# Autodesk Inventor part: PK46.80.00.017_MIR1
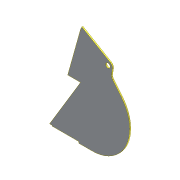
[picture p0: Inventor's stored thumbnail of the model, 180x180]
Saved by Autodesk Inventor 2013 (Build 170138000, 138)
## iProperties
Created: 2004-12
Part Number: PK46.80.00.017_MIR1
Material: Steel, Mild
Document SubType Name: Modeling
Designer: hoeyj
Manufacturer: Standard
Standards Organization: Custom
Density: 7.86 g/cm^3
Mass: 57972.3 g
Surface Area: 12737.7 cm^2
Volume: 7375.62 cm^3
Author: Salex
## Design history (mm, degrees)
derived "PK46.80.00.017.ipt"
  sketch "Sketch1"
    geometry: L1 (384.873, 16.042)-(239.873, 536.042) reference; L2 (239.873, 536.042)-(224.873, 566.042) reference; L3 (224.873, 566.042)-(-95.324, 379.229) reference; L4 (109.873, -588.958)-(259.873, -588.958) reference; L5 (589.873, -563.958)-(239.873, 16.042) reference; L6 (239.873, 16.042)-(384.873, 16.042) reference; L7 (-218.934, 105.321)-(-121.444, 224.362) reference; L8 (-110.587, 262.81)-(-119.667, 329.274) reference; L9 (589.873, -563.958)-(559.873, -563.958) reference; L10 (559.873, -563.958)-(559.873, -571.958) reference; L11 (559.873, -571.958)-(259.873, -571.958) reference; L12 (259.873, -571.958)-(259.873, -588.958) reference; L13 (239.873, 16.042)-(149.815, -38.304) reference; C1 r 25 at (-70.127, 336.042) reference; A1 r 425 centre (109.873, -163.958) between (-218.934, 105.321) and (109.873, -588.958) reference; A2 r 50 centre (-160.127, 256.042) between (-121.444, 224.362) and (-110.587, 262.81) reference; A3 r 50 centre (-70.127, 336.042) between (-95.324, 379.229) and (-119.667, 329.274) reference; 1 further point
body "Solid1"
tag "TaggingFeature3"
feature "DerivedBody::PK46.80.00.017.ipt" dims "d0" = 10
